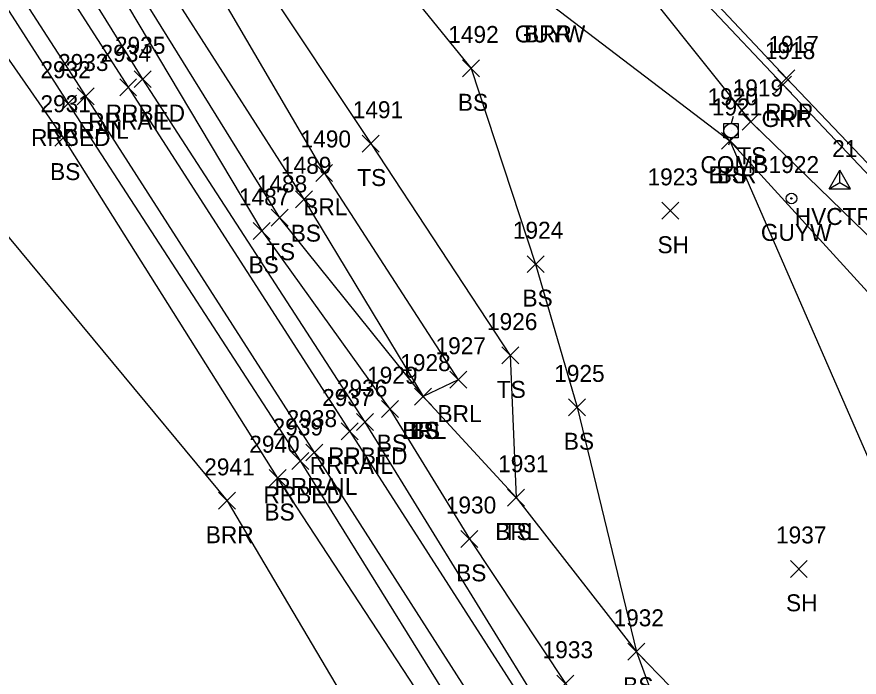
# Model space of a CAD drawing. Extents: x 1505656 to 1508446, y 700805 to 703031.
# Drawn here: x 1506356.7 to 1506456, y 701922.6 to 702000.4 of the extents above; entities that cross this region are included whole.
import ezdxf

# ---------------------------------------------------------------- set-up
doc = ezdxf.new("R2010")
doc.units = 0
for name, color, linetype in [('C_A', 7, 'Continuous'), ('C_I', 7, 'Continuous'), ('CPSM', 7, 'Continuous'), ('L_A', 7, 'Continuous'), ('L_I', 7, 'Continuous'), ('L_TIC', 7, 'Continuous'), ('LABL', 7, 'Continuous'), ('LELB', 7, 'Continuous'), ('P_A', 7, 'Continuous'), ('P_I', 7, 'Continuous'), ('P_TIC', 7, 'Continuous'), ('PET', 7, 'Continuous'), ('R_A', 7, 'Continuous'), ('R_I', 7, 'Continuous'), ('R_TIC', 7, 'Continuous'), ('RGR', 7, 'Continuous'), ('RR', 7, 'Continuous'), ('RRB', 7, 'Continuous'), ('U_A', 7, 'Continuous'), ('U_I', 7, 'Continuous'), ('UP', 7, 'Continuous'), ('UPGW', 7, 'Continuous')]:
    doc.layers.add(name, color=color, linetype=linetype)

msp = doc.modelspace()

# ---------------------------------------------------------------- linework, layer by layer
at = {"layer": 'CPSM'}
for p, q in [((1506452.499, 701980.159), (1506453.749, 701982.324)), ((1506454.999, 701980.159), (1506453.749, 701982.324)), ((1506453.749, 701980.88), (1506453.749, 701982.324)), ((1506452.499, 701980.159), (1506453.749, 701980.88)), ((1506453.749, 701980.88), (1506453.749, 701980.88)), ((1506453.749, 701980.88), (1506454.999, 701980.159)), ((1506452.499, 701980.159), (1506454.999, 701980.159))]:
    msp.add_line(p, q, dxfattribs=at)
at = {"layer": 'L_TIC'}
for points in [[(1506409.258, 701993.342), (1506411.258, 701995.342)], [(1506411.258, 701993.342), (1506409.258, 701995.342)], [(1506442.257, 701987.04), (1506444.257, 701989.04)], [(1506444.257, 701987.04), (1506442.257, 701989.04)], [(1506361.149, 701985.17), (1506363.149, 701987.17)], [(1506363.149, 701985.17), (1506361.149, 701987.17)], [(1506439.789, 701984.798), (1506441.789, 701986.798)], [(1506441.789, 701984.798), (1506439.789, 701986.798)], [(1506439.789, 701984.798), (1506441.789, 701986.798)], [(1506441.789, 701984.798), (1506439.789, 701986.798)], [(1506397.42, 701984.471), (1506399.42, 701986.471)], [(1506399.42, 701984.471), (1506397.42, 701986.471)], [(1506391.925, 701981.024), (1506393.925, 701983.024)], [(1506393.925, 701981.024), (1506391.925, 701983.024)], [(1506389.538, 701977.915), (1506391.538, 701979.915)], [(1506391.538, 701977.915), (1506389.538, 701979.915)], [(1506432.762, 701976.549), (1506434.762, 701978.549)], [(1506434.762, 701976.549), (1506432.762, 701978.549)], [(1506386.67, 701975.728), (1506388.67, 701977.728)], [(1506388.67, 701975.728), (1506386.67, 701977.728)], [(1506384.569, 701974.184), (1506386.569, 701976.184)], [(1506386.569, 701974.184), (1506384.569, 701976.184)], [(1506384.569, 701974.184), (1506386.569, 701976.184)], [(1506386.569, 701974.184), (1506384.569, 701976.184)], [(1506416.876, 701970.258), (1506418.876, 701972.258)], [(1506418.876, 701970.258), (1506416.876, 701972.258)], [(1506413.884, 701959.491), (1506415.884, 701961.491)], [(1506415.884, 701959.491), (1506413.884, 701961.491)], [(1506407.752, 701956.634), (1506409.752, 701958.634)], [(1506409.752, 701956.634), (1506407.752, 701958.634)], [(1506403.597, 701954.648), (1506405.597, 701956.648)], [(1506405.597, 701954.648), (1506403.597, 701956.648)], [(1506403.597, 701954.648), (1506405.597, 701956.648)], [(1506405.597, 701954.648), (1506403.597, 701956.648)], [(1506403.597, 701954.648), (1506405.597, 701956.648)], [(1506405.597, 701954.648), (1506403.597, 701956.648)], [(1506399.692, 701953.164), (1506401.692, 701955.164)], [(1506401.692, 701953.164), (1506399.692, 701955.164)], [(1506399.692, 701953.164), (1506401.692, 701955.164)], [(1506401.692, 701953.164), (1506399.692, 701955.164)], [(1506421.757, 701953.376), (1506423.757, 701955.376)], [(1506423.757, 701953.376), (1506421.757, 701955.376)], [(1506386.438, 701945.028), (1506388.438, 701947.028)], [(1506388.438, 701945.028), (1506386.438, 701947.028)], [(1506380.471, 701942.354), (1506382.471, 701944.354)], [(1506382.471, 701942.354), (1506380.471, 701944.354)], [(1506414.573, 701942.724), (1506416.573, 701944.724)], [(1506416.573, 701942.724), (1506414.573, 701944.724)], [(1506414.573, 701942.724), (1506416.573, 701944.724)], [(1506416.573, 701942.724), (1506414.573, 701944.724)], [(1506409.052, 701937.855), (1506411.052, 701939.855)], [(1506411.052, 701937.855), (1506409.052, 701939.855)], [(1506447.925, 701934.326), (1506449.925, 701936.326)], [(1506449.925, 701934.326), (1506447.925, 701936.326)], [(1506428.754, 701924.555), (1506430.754, 701926.555)], [(1506430.754, 701924.555), (1506428.754, 701926.555)], [(1506428.754, 701924.555), (1506430.754, 701926.555)], [(1506430.754, 701924.555), (1506428.754, 701926.555)], [(1506420.393, 701920.793), (1506422.393, 701922.793)], [(1506422.393, 701920.793), (1506420.393, 701922.793)]]:
    msp.add_lwpolyline(points, dxfattribs=at)
at = {"layer": 'LABL'}
for points in [[(1506097.891, 702451.479), (1506093.586, 702448.306), (1506114.072, 702419.305), (1506137.715, 702376.045), (1506165.525, 702335.143), (1506176.551, 702314.381), (1506188.561, 702296.456), (1506197.642, 702285.718), (1506210.238, 702262.449), (1506236.391, 702222.105), (1506262.975, 702180.707), (1506287.878, 702142.766), (1506318.295, 702098.355), (1506343.911, 702058.606), (1506370.149, 702020.942), (1506392.925, 701982.024), (1506408.752, 701957.634), (1506404.597, 701955.648), (1506415.573, 701943.724), (1506429.754, 701925.555), (1506437.711, 701917.365), (1506453.701, 701897.967), (1506473.578, 701870.512), (1506501.095, 701826.995)], [(1506097.891, 702451.479), (1506119.326, 702422.589), (1506147.143, 702381.233), (1506170.739, 702339.268), (1506181.047, 702317.334), (1506195.309, 702300.853), (1506204.63, 702289.221), (1506217.936, 702268.002), (1506249.758, 702230.45), (1506275.61, 702192.019), (1506301.13, 702151.48), (1506333.13, 702110.445), (1506362.684, 702074.768), (1506393.244, 702036.244), (1506419.011, 702002.404), (1506440.789, 701985.798), (1506459.199, 701943.611), (1506474.51, 701912.206), (1506491.957, 701880.663), (1506505.674, 701860.234), (1506521.401, 701845.883), (1506529.177, 701832.12), (1506516.383, 701828.815), (1506501.095, 701826.995)], [(1506270.222, 702103.444), (1506301.767, 702060.126), (1506327.617, 702017.85), (1506352.125, 701978.72), (1506381.471, 701943.354), (1506404.219, 701904.968), (1506405.418, 701902.639), (1506427.035, 701865.87), (1506439.871, 701843.692), (1506458.472, 701818.081), (1506448.558, 701811.949), (1506441.614, 701824.073), (1506420.952, 701839.987), (1506407.537, 701857.979)]]:
    msp.add_lwpolyline(points, dxfattribs=at)
at = {"layer": 'LELB'}
for points in [[(1505941.536, 702671.126), (1505960.905, 702641.209), (1505983.848, 702606.414), (1506009.662, 702565.578), (1506036.171, 702525.552), (1506062.346, 702483.612), (1506087.3, 702443.663), (1506107.025, 702410.494), (1506132.096, 702372.933), (1506158.965, 702331.11), (1506171.726, 702310.513), (1506183.603, 702292.092), (1506190.679, 702281.135), (1506204.659, 702258.806), (1506230.375, 702218.876), (1506257.753, 702177.435), (1506282.281, 702138.539), (1506311.276, 702093.483), (1506337.325, 702051.881), (1506360.109, 702017.936), (1506385.569, 701975.184)], [(1506201.907, 702312.635), (1506228.688, 702274.023), (1506255.113, 702234.426), (1506278.209, 702201.234), (1506308.431, 702156.122), (1506338.791, 702114.368), (1506367.336, 702079.99), (1506400.017, 702040.528), (1506426.305, 702009.283), (1506443.257, 701988.04), (1506472.877, 701959.313), (1506500.815, 701931.78), (1506527.025, 701905.238), (1506551.996, 701883.977), (1506559.853, 701877.072), (1506564.801, 701867.875), (1506566.198, 701856.006), (1506560.037, 701843.77), (1506551.045, 701834.869), (1506537.765, 701828.439), (1506532.338, 701826.513)], [(1506188.561, 702296.456), (1506192.934, 702283.039), (1506207.332, 702260.501), (1506233.604, 702220.789), (1506259.915, 702179.297), (1506284.931, 702140.804), (1506313.826, 702095.76), (1506340.971, 702055.872), (1506361.093, 702019.604), (1506387.67, 701976.728), (1506404.597, 701955.648)], [(1506217.936, 702268.002), (1506241.751, 702226.262), (1506266.606, 702184.288), (1506291.505, 702144.914), (1506326.974, 702105.861), (1506352.657, 702068.74), (1506380.93, 702030.463), (1506410.258, 701994.342), (1506417.876, 701971.258), (1506422.757, 701954.376), (1506429.754, 701925.555), (1506435.035, 701911.198)], [(1506208.26, 702225.335), (1506233.066, 702186.127), (1506256.11, 702150.879), (1506281.705, 702110.75), (1506310.98, 702065.972), (1506335.891, 702023.858), (1506362.149, 701986.17), (1506387.438, 701946.028), (1506412.525, 701907.733), (1506436.182, 701872.353), (1506448.776, 701849.495), (1506468, 701820.558), (1506480.93, 701799.854), (1506497.591, 701775.161), (1506503.349, 701767.24), (1506509.308, 701758.888), (1506523.549, 701737.243), (1506530.483, 701722.023), (1506538.471, 701708.022), (1506540.166, 701706.711), (1506553.683, 701688.505), (1506562.308, 701674.175), (1506570.511, 701664.867), (1506574.8, 701654.407)], [(1506343.911, 702058.606), (1506372.567, 702024.35), (1506398.42, 701985.471), (1506414.884, 701960.491), (1506415.573, 701943.724)], [(1506370.149, 702020.942), (1506364.703, 702019.302), (1506390.538, 701978.915), (1506404.597, 701955.648)], [(1506440.789, 701985.798), (1506469.226, 701954.62)], [(1506385.569, 701975.184), (1506400.692, 701954.164)], [(1506400.692, 701954.164), (1506410.052, 701938.855), (1506421.393, 701921.793), (1506431.568, 701906.51), (1506444.826, 701885.849), (1506459.474, 701862.217), (1506475.182, 701837.451), (1506488.216, 701817.667), (1506493.054, 701810.169), (1506509.384, 701784.616), (1506521.059, 701767.791), (1506521.669, 701765.32), (1506527.402, 701761.586), (1506541.412, 701751.984), (1506556.286, 701742.029), (1506568.248, 701733.503), (1506577.204, 701727.116), (1506582.741, 701726.246), (1506593.973, 701725.769), (1506597.624, 701726.249), (1506603.473, 701725.818)]]:
    msp.add_lwpolyline(points, dxfattribs=at)
at = {"layer": 'P_TIC'}
for points in [[(1506446.463, 701992.175), (1506448.463, 701994.175)], [(1506448.463, 701992.175), (1506446.463, 701994.175)]]:
    msp.add_lwpolyline(points, dxfattribs=at)
at = {"layer": 'PET'}
msp.add_lwpolyline([(1506206.188, 702315.609), (1506232.667, 702276.153), (1506258.725, 702236.985), (1506281.311, 702203.576), (1506312.12, 702158.402), (1506342.493, 702116.71), (1506370.71, 702081.777), (1506402.647, 702042.722), (1506430.056, 702011.73), (1506447.463, 701993.175), (1506476.848, 701962.379), (1506503.963, 701935.538), (1506531.718, 701909.612)], dxfattribs=at)
at = {"layer": 'R_TIC'}
for points in [[(1506370.505, 701992.069), (1506372.505, 701994.069)], [(1506372.505, 701992.069), (1506370.505, 701994.069)], [(1506368.803, 701991.121), (1506370.803, 701993.121)], [(1506370.803, 701991.121), (1506368.803, 701993.121)], [(1506446.039, 701991.434), (1506448.039, 701993.434)], [(1506448.039, 701991.434), (1506446.039, 701993.434)], [(1506363.792, 701990.038), (1506365.792, 701992.038)], [(1506365.792, 701990.038), (1506363.792, 701992.038)], [(1506361.71, 701989.183), (1506363.71, 701991.183)], [(1506363.71, 701989.183), (1506361.71, 701991.183)], [(1506396.737, 701951.642), (1506398.737, 701953.642)], [(1506398.737, 701951.642), (1506396.737, 701953.642)], [(1506394.941, 701950.532), (1506396.941, 701952.532)], [(1506396.941, 701950.532), (1506394.941, 701952.532)], [(1506390.761, 701948.048), (1506392.761, 701950.048)], [(1506392.761, 701948.048), (1506390.761, 701950.048)], [(1506389.113, 701947.059), (1506391.113, 701949.059)], [(1506391.113, 701947.059), (1506389.113, 701949.059)]]:
    msp.add_lwpolyline(points, dxfattribs=at)
at = {"layer": 'RGR'}
msp.add_lwpolyline([(1506194.429, 702325.739), (1506204.07, 702314.524), (1506231.72, 702275.449), (1506257.865, 702236.544), (1506280.914, 702202.923), (1506311.025, 702157.692), (1506341.898, 702115.676), (1506369.199, 702080.673), (1506401.884, 702042.274), (1506429.345, 702011.198), (1506447.039, 701992.434), (1506475.964, 701961.849), (1506503.455, 701934.999), (1506530.822, 701909.192), (1506554.476, 701886.522), (1506561.677, 701878.563), (1506566.908, 701868.507), (1506568.014, 701855.173), (1506562.315, 701841.05), (1506554.986, 701832.495), (1506533.66, 701824.882)], dxfattribs=at)
at = {"layer": 'RR'}
for points in [[(1506216.216, 702230.609), (1506241.138, 702191.913), (1506264.218, 702156.052), (1506289.374, 702116.983), (1506318.675, 702071.08), (1506345.503, 702029.867), (1506369.803, 701992.121), (1506395.941, 701951.532), (1506421.294, 701912.094)], [(1506212.178, 702227.875), (1506237.14, 702189.064), (1506259.993, 702153.601), (1506285.641, 702113.676), (1506314.244, 702068.629), (1506341.493, 702027.055), (1506364.792, 701991.038), (1506391.761, 701949.048), (1506416.431, 701910.499)]]:
    msp.add_lwpolyline(points, dxfattribs=at)
at = {"layer": 'RRB'}
for points in [[(1506218.207, 702231.869), (1506243.423, 702192.986), (1506265.645, 702156.973), (1506291.152, 702118.107), (1506320.482, 702072.195), (1506347.645, 702031.42), (1506371.505, 701993.069), (1506397.737, 701952.642), (1506422.134, 701913.025), (1506446.302, 701877.372), (1506459.904, 701856.601), (1506479.197, 701826.274), (1506491.068, 701808.201), (1506507.805, 701783.164), (1506518.904, 701765.849), (1506532.833, 701744.112), (1506551.138, 701715.117), (1506563.365, 701695.789), (1506572.4, 701681.686), (1506577.693, 701674.709), (1506587.051, 701661.961)], [(1506210.032, 702226.699), (1506235.369, 702188.006), (1506257.817, 702152.359), (1506283.918, 702112.551), (1506312.529, 702067.455), (1506339.769, 702025.985), (1506362.71, 701990.183), (1506390.113, 701948.059), (1506413.744, 701910.016), (1506437.483, 701874.064), (1506451.694, 701851.337), (1506470.612, 701821.885), (1506483.367, 701801.538), (1506500.232, 701776.891), (1506510.87, 701759.997), (1506525.082, 701738.282), (1506533.528, 701723.993), (1506542.091, 701710.784), (1506543.896, 701708.677), (1506555.777, 701690.222), (1506571.644, 701665.343), (1506576.241, 701655.226)]]:
    msp.add_lwpolyline(points, dxfattribs=at)
at = {"layer": 'UP'}
for p, q in [((1506440.093, 701986.161), (1506440.093, 701987.827)), ((1506440.093, 701987.827), (1506441.759, 701987.827)), ((1506441.176, 701988.661), (1506440.926, 701987.827)), ((1506441.759, 701987.827), (1506441.759, 701986.161)), ((1506440.926, 701986.994), (1506440.926, 701986.994)), ((1506441.759, 701986.161), (1506440.093, 701986.161)), ((1506440.676, 701985.327), (1506440.926, 701986.161))]:
    msp.add_line(p, q, dxfattribs=at)
msp.add_circle((1506440.926, 701986.994), 0.833, dxfattribs=at)
at = {"layer": 'UPGW'}
for radius in [0.625, 0.0833]:
    msp.add_circle((1506448.053, 701979.002), radius, dxfattribs=at)

# ---------------------------------------------------------------- texts
at = {"layer": 'C_A'}
msp.add_text('HVCTRL', height=2, dxfattribs=at).set_placement((1506448.442, 701975.88))
at = {"layer": 'C_I'}
msp.add_text('21', height=2, dxfattribs=at).set_placement((1506452.851, 701983.88))
at = {"layer": 'L_A'}
for s, p in [('BRR', (1506416.499, 701997.404)), ('BS', (1506408.699, 701989.342)), ('TS', (1506441.666, 701983.04)), ('BS', (1506360.59, 701981.17)), ('BRR', (1506438.277, 701980.798)), ('BS', (1506439.23, 701980.798)), ('TS', (1506396.829, 701980.471)), ('BRL', (1506390.468, 701977.024)), ('BS', (1506388.979, 701973.915)), ('SH', (1506432.25, 701972.549)), ('TS', (1506386.079, 701971.728)), ('BS', (1506384.01, 701970.184)), ('BS', (1506384.01, 701970.184)), ('BS', (1506416.317, 701966.258)), ('TS', (1506413.294, 701955.491)), ('BRL', (1506406.295, 701952.634)), ('BRL', (1506402.141, 701950.648)), ('TS', (1506403.007, 701950.648)), ('BS', (1506403.038, 701950.648)), ('BS', (1506399.133, 701949.164)), ('BS', (1506399.133, 701949.164)), ('BS', (1506421.198, 701949.376)), ('BS', (1506385.879, 701941.028)), ('BRR', (1506378.959, 701938.354)), ('BRL', (1506413.116, 701938.724)), ('TS', (1506413.982, 701938.724)), ('BS', (1506408.493, 701933.855)), ('SH', (1506447.413, 701930.326)), ('BS', (1506428.195, 701920.555))]:
    msp.add_text(s, height=2, dxfattribs=at).set_placement(p)
at = {"layer": 'L_I'}
for s, p in [('1492', (1506407.565, 701997.342)), ('1919', (1506441.123, 701991.04)), ('2931', (1506359.456, 701989.17)), ('1921', (1506438.663, 701988.798)), ('1921', (1506438.663, 701988.798)), ('1491', (1506396.294, 701988.471)), ('1490', (1506390.145, 701985.024)), ('1489', (1506387.837, 701981.915)), ('1923', (1506431.069, 701980.549)), ('1488', (1506384.977, 701979.728)), ('1487', (1506382.876, 701978.184)), ('1487', (1506382.876, 701978.184)), ('1924', (1506415.183, 701974.258)), ('1926', (1506412.136, 701963.491)), ('1927', (1506406.059, 701960.634)), ('1928', (1506401.905, 701958.648)), ('1928', (1506401.905, 701958.648)), ('1928', (1506401.905, 701958.648)), ('1929', (1506397.991, 701957.164)), ('1929', (1506397.991, 701957.164)), ('1925', (1506420.064, 701957.376)), ('2940', (1506384.091, 701949.028)), ('2941', (1506378.778, 701946.354)), ('1931', (1506413.447, 701946.724)), ('1931', (1506413.447, 701946.724)), ('1930', (1506407.273, 701941.855)), ('1937', (1506446.232, 701938.326)), ('1932', (1506427.061, 701928.555)), ('1932', (1506427.061, 701928.555)), ('1933', (1506418.7, 701924.793))]:
    msp.add_text(s, height=2, dxfattribs=at).set_placement(p)
at = {"layer": 'P_A'}
msp.add_text('RDP', height=2, dxfattribs=at).set_placement((1506444.951, 701988.175))
at = {"layer": 'P_I'}
msp.add_text('1917', height=2, dxfattribs=at).set_placement((1506445.337, 701996.175))
at = {"layer": 'R_A'}
for s, p in [('RRBED', (1506367.15, 701988.069)), ('RRRAIL', (1506365.094, 701987.121)), ('GRR', (1506444.527, 701987.434)), ('RRRAIL', (1506360.084, 701986.038)), ('RRBED', (1506358.355, 701985.183)), ('RRBED', (1506393.383, 701947.642)), ('RRRAIL', (1506391.232, 701946.532)), ('RRRAIL', (1506387.052, 701944.048)), ('RRBED', (1506385.759, 701943.059))]:
    msp.add_text(s, height=2, dxfattribs=at).set_placement(p)
at = {"layer": 'R_I'}
for s, p in [('2935', (1506368.245, 701996.069)), ('2934', (1506366.543, 701995.121)), ('1918', (1506444.913, 701995.434)), ('2933', (1506361.533, 701994.038)), ('2932', (1506359.45, 701993.183)), ('2936', (1506394.422, 701955.642)), ('2937', (1506392.681, 701954.532)), ('2938', (1506388.501, 701952.048)), ('2939', (1506386.846, 701951.059))]:
    msp.add_text(s, height=2, dxfattribs=at).set_placement(p)
at = {"layer": 'U_A'}
for s, p in [('GUYW', (1506415.405, 701997.404)), ('COMB', (1506437.312, 701981.994)), ('GUYW', (1506444.447, 701974.002))]:
    msp.add_text(s, height=2, dxfattribs=at).set_placement(p)
at = {"layer": 'U_I'}
for s, p in [('1920', (1506438.146, 701989.994)), ('1922', (1506445.36, 701982.002))]:
    msp.add_text(s, height=2, dxfattribs=at).set_placement(p)

doc.saveas('drawing.dxf')
